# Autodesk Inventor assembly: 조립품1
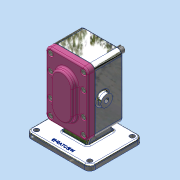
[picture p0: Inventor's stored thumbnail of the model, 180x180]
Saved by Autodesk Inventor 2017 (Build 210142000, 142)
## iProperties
Part Number: 조립품1
Material: 일반
Document SubType Name: Assembly
Designer: MRC
Author: MRC
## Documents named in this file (11)
- C:\Users\MRC\Desktop\700407V1046\조립품1.iam
- C:\Users\MRC\Desktop\700407V1046\본체.ipt
- C:\Users\MRC\Desktop\700407V1046\개스킷.ipt
- C:\Users\MRC\Desktop\700407V1046\메인축.ipt
- C:\Users\MRC\Desktop\700407V1046\베어링부시.ipt
- C:\Users\MRC\Desktop\700407V1046\볼트 M5.ipt
- C:\Users\MRC\Desktop\700407V1046\서브축.ipt
- C:\Users\MRC\Desktop\700407V1046\스퍼기어.ipt
- C:\Users\MRC\Desktop\700407V1046\오일 실 16 28 7.ipt
- C:\Users\MRC\Desktop\700407V1046\커버.ipt
- C:\Users\MRC\Desktop\700407V1046\키 6 x 6 x 18.ipt
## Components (1 placed, 1 different names)
1. 개스킷:1
